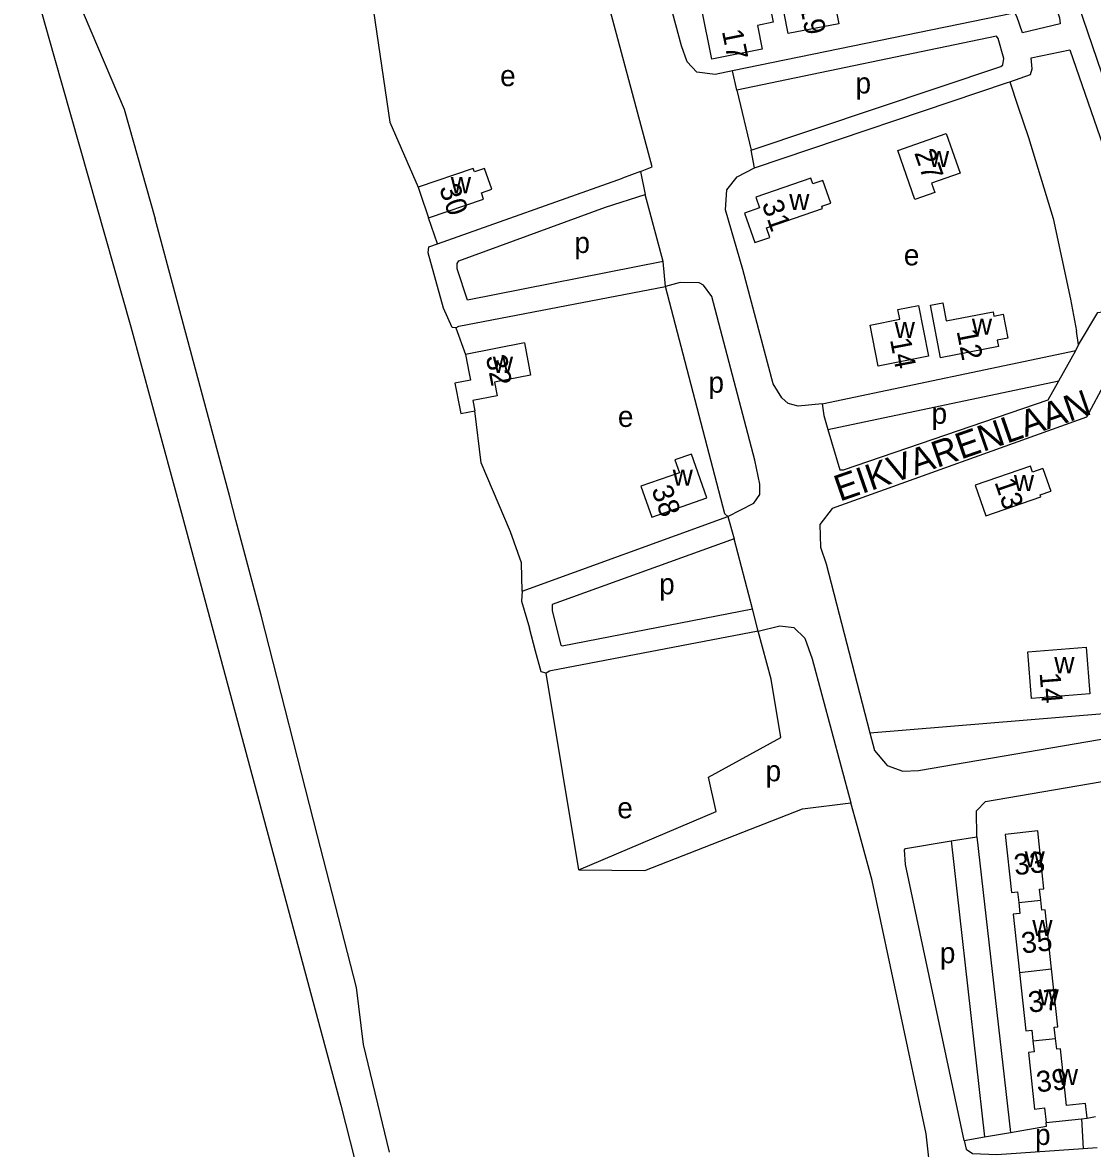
# Model space of a CAD drawing. Extents: x 162667 to 164645, y 379003 to 382150.
# Drawn here: x 162748.4 to 162953, y 380351.9 to 380567.1 of the extents above; entities that cross this region are included whole.
import ezdxf

# ---------------------------------------------------------------- set-up
doc = ezdxf.new("R2010")
doc.units = 0
for name, color, linetype in [('BLT_Basislijn', 7, 'Continuous'), ('BLT_Bebouwing', 7, 'Continuous'), ('BLT_Centroide', 7, 'Continuous'), ('BLT_Huisnummer', 7, 'Continuous'), ('BLT_Onderverdeling_panden', 7, 'Continuous'), ('BLT_Straatnaam', 7, 'Continuous')]:
    doc.layers.add(name, color=color, linetype=linetype)

msp = doc.modelspace()

# ---------------------------------------------------------------- linework, layer by layer
at = {"layer": 'BLT_Basislijn'}
for p, q in [((162885, 380554.15), (162884.15, 380557.88)), ((162885, 380554.15), (162887.73, 380542.69)), ((162937.23, 380555.78), (162938.71, 380551.1)), ((162938.71, 380551.1), (162940.78, 380545.13)), ((162888.4, 380539.33), (162887.73, 380542.69)), ((162866.54, 380538.63), (162863.1, 380537.35)), ((162866.54, 380538.63), (162867.49, 380534.23)), ((162870.88, 380521.4), (162867.49, 380534.23)), ((162777.53, 380515.53), (162773.77, 380529.55)), ((162827.72, 380524.79), (162826.04, 380529.74)), ((162779.18, 380509.37), (162777.53, 380515.53)), ((162948.79, 380514.24), (162949.98, 380508.1)), ((162788.01, 380476.4), (162779.18, 380509.37)), ((162831.23, 380508.73), (162833.08, 380503.66)), ((162950.31, 380505.48), (162949.98, 380508.1)), ((162949.82, 380504.43), (162950.31, 380505.48)), ((162901.33, 380494.19), (162949.82, 380504.43)), ((162946.55, 380498.63), (162949.82, 380504.43)), ((162902.39, 380489.31), (162946.55, 380498.63)), ((162789.2, 380471.99), (162788.01, 380476.4)), ((162843.96, 380458.41), (162883.27, 380472.69)), ((162794.06, 380453.83), (162789.2, 380471.99)), ((162888.01, 380455.04), (162884.51, 380468.41)), ((162889.08, 380450.77), (162888.01, 380455.04)), ((162846.5, 380446.93), (162845.32, 380451.31)), ((162889.08, 380450.77), (162849.44, 380443.15)), ((162891.58, 380441.6), (162889.08, 380450.77)), ((162854.78, 380405.1), (162848.53, 380442.72)), ((162908.01, 380413.59), (162906.8, 380417.91)), ((162925.98, 380410.64), (162930.92, 380411.44)), ((162925.98, 380410.64), (162932.37, 380354.06)), ((162930.92, 380411.44), (162937.3, 380354.9)), ((162937.3, 380354.9), (162944.19, 380356.11)), ((162944.19, 380356.11), (162944.14, 380356.82)), ((162950.88, 380357.55), (162951.2, 380351.88)), ((162952, 380357.67), (162953.61, 380357.95)), ((162928.48, 380353.4), (162932.37, 380354.06)), ((162932.37, 380354.06), (162937.3, 380354.9))]:
    msp.add_line(p, q, dxfattribs=at)
for points in [[(162928.15, 380621.89), (162946.67, 380568), (162946.84, 380566.84), (162939.62, 380565.1), (162938.53, 380568.25), (162938.19, 380568.83), (162937.65, 380568.79), (162884.15, 380557.88)], [(162936.69, 380610.36), (162967.4, 380520.31), (162968.51, 380517.36), (162969.4, 380517.45), (162963.56, 380600.72), (162963.48, 380601.84)], [(162884.15, 380557.88), (162880.85, 380557.13), (162877.35, 380557.61), (162875.5, 380559.58), (162874.39, 380562.61), (162866.41, 380592.44), (162865.65, 380596.55), (162865.67, 380598.15), (162867.28, 380600.7), (162871.18, 380602.46)], [(162748.39, 380581.99), (162754.35, 380560.74), (162769.12, 380508.9), (162778.96, 380472.61)], [(162866.54, 380538.63), (162868.78, 380539.48), (162857.1, 380583.31)], [(162758.91, 380571.59), (162767.84, 380550.54), (162773.77, 380529.55)], [(162815.54, 380569.25), (162818.61, 380548.05), (162824.03, 380535.6)], [(162887.73, 380542.69), (162935.51, 380558.69), (162935.89, 380559.01), (162936.05, 380560.22), (162934.95, 380564.02), (162934.66, 380564.49), (162885, 380554.15)], [(162937.23, 380555.78), (162941.15, 380557.19), (162941.47, 380558.24), (162941.29, 380560.34), (162948.69, 380561.9), (162965.48, 380513.26)], [(162888.4, 380539.33), (162936.77, 380555.61), (162937.23, 380555.78)], [(162940.78, 380545.13), (162945.46, 380529.62), (162948.79, 380514.24)], [(162901.33, 380494.19), (162896.71, 380493.73), (162894.78, 380494.25), (162893.57, 380495.35), (162891.95, 380498.06), (162886.17, 380519.88), (162882.83, 380531.28), (162883.05, 380535.14), (162885.06, 380537.62), (162888.4, 380539.33)], [(162827.72, 380524.79), (162862.22, 380537.03), (162863.1, 380537.35)], [(162870.88, 380521.4), (162833.46, 380514), (162831.53, 380520.01), (162831.52, 380521.02), (162831.84, 380521.56), (162859.87, 380531.77), (162867.49, 380534.23)], [(162831.23, 380508.73), (162830.54, 380508.82), (162828.92, 380512.51), (162825.95, 380523.07), (162826.08, 380524.21), (162827.72, 380524.79)], [(162871.37, 380516.62), (162870.88, 380521.4)], [(162831.23, 380508.73), (162831.81, 380509.06), (162871.37, 380516.62)], [(162883.27, 380472.69), (162888.25, 380475.19), (162889.36, 380476.88), (162889.36, 380478.87), (162888.46, 380483.45), (162880.24, 380514.71), (162878.62, 380516.88), (162877.76, 380517.36), (162874.18, 380517.39), (162871.37, 380516.62)], [(162883.27, 380472.69), (162882.73, 380473.17), (162871.37, 380516.62)], [(162950.31, 380505.48), (162954.06, 380511.67), (162965.48, 380513.26)], [(162955.48, 380498.39), (162951.83, 380491.64), (162903.21, 380474.17), (162900.87, 380471.11), (162901, 380466.81), (162902.05, 380463.65), (162910.44, 380431.3)], [(162902.39, 380489.31), (162904.66, 380481.58), (162905.36, 380481.57), (162944.5, 380495), (162946.55, 380498.63)], [(162901.33, 380494.19), (162901.61, 380491.97), (162902.39, 380489.31)], [(162841.72, 380469.75), (162836.09, 380482.9), (162834.89, 380492.87)], [(162778.96, 380472.61), (162809.27, 380360.13), (162814.71, 380338.87)], [(162883.27, 380472.69), (162884.51, 380468.41)], [(162843.96, 380458.41), (162843.79, 380463.84), (162841.72, 380469.75)], [(162884.51, 380468.41), (162849.68, 380455.85), (162849.68, 380454.63), (162851.34, 380448.1), (162851.6, 380447.94), (162888.01, 380455.04)], [(162843.96, 380458.41), (162843.83, 380456.48), (162845.32, 380451.31)], [(162818.56, 380351.15), (162813.62, 380371.74), (162812.27, 380382.63), (162804.82, 380411.61), (162794.06, 380453.83)], [(162889.08, 380450.77), (162893.19, 380451.79), (162895.89, 380451.43), (162897.97, 380449.4), (162899.4, 380445.49), (162906.8, 380417.91)], [(162910.44, 380431.3), (162955.18, 380435.03), (162955.09, 380438.8), (162955.53, 380438.88), (162996.45, 380442.3), (162996.77, 380442.68), (162996.75, 380446.24), (163038.61, 380449.48)], [(162910.44, 380431.3), (162911.35, 380427.96), (162913.74, 380425.09), (162916.71, 380423.98), (162919.74, 380424.13), (162954.37, 380430.01), (163031.14, 380443.68), (163034.88, 380444.59), (163036.92, 380445.42), (163038.2, 380446.92), (163038.61, 380449.48)], [(162848.53, 380442.72), (162847.59, 380442.99), (162846.5, 380446.93)], [(162849.44, 380443.15), (162849.19, 380443.1), (162848.53, 380442.72)], [(162854.78, 380405.1), (162881.05, 380416.29), (162879.57, 380422.81), (162893.41, 380430.42), (162891.58, 380441.6)], [(162930.92, 380411.44), (162930.8, 380416.43), (162932.55, 380418.18), (162970.08, 380424.65), (162975.1, 380425.17), (162976.67, 380424.93), (162978.44, 380423.02), (162979.49, 380419.64)], [(162854.78, 380405.1), (162867.37, 380404.98), (162897.55, 380416.8), (162906.8, 380417.91)], [(162923.85, 380330.61), (162921.23, 380354.66), (162910.88, 380403.1), (162908.01, 380413.59)], [(162928.48, 380353.4), (162917.27, 380406.15), (162917.06, 380408.95), (162917.25, 380409.22), (162925.98, 380410.64)], [(162928.48, 380353.4), (162928.88, 380351.73), (162930.06, 380350.88), (162934.73, 380350.71), (162951.2, 380351.88)], [(162951.2, 380351.88), (162953.93, 380352.07)]]:
    msp.add_lwpolyline(points, dxfattribs=at)
at = {"layer": 'BLT_Bebouwing'}
for p, q in [((162935.94, 380511.32), (162936.82, 380506.77)), ((162844.37, 380505.85), (162833.08, 380503.66)), ((162943.54, 380481.86), (162945.03, 380477.54)), ((162944.14, 380356.82), (162950.88, 380357.55)), ((162950.88, 380357.55), (162952, 380357.67))]:
    msp.add_line(p, q, dxfattribs=at)
for points in [[(162893.31, 380572.83), (162898.97, 380573.94), (162898.61, 380575.8), (162902.57, 380576.58), (162904.47, 380566.86), (162894.84, 380564.98)], [(162878.24, 380569.9), (162887.77, 380571.77), (162887.21, 380574.61), (162890.35, 380575.24), (162891.96, 380567.16), (162888.92, 380566.55), (162889.83, 380561.98), (162880.23, 380560.07)], [(162915.79, 380542.63), (162925.05, 380545.86), (162927.68, 380538.3), (162922.23, 380536.41), (162922.85, 380534.61), (162919.05, 380533.28)], [(162919.76, 380513.01), (162921.67, 380503.3), (162912.03, 380501.41), (162910.51, 380509.25), (162916.16, 380510.36), (162915.79, 380512.23)], [(162940.64, 380446.8), (162951.8, 380447.67), (162952.5, 380438.75), (162941.34, 380437.87)]]:
    msp.add_lwpolyline(points, close=True, dxfattribs=at)
for points in [[(162838.14, 380535.22), (162836.77, 380539.21), (162834.82, 380538.54), (162834.58, 380539.22), (162824.03, 380535.6)], [(162901.46, 380536.92), (162899.5, 380536.24), (162899.12, 380537.34), (162888.64, 380533.72), (162889.34, 380531.67), (162886.49, 380530.68), (162888.45, 380525.02), (162891.29, 380526), (162890.66, 380527.83), (162901.36, 380531.53), (162901.25, 380531.98), (162902.96, 380532.58)], [(162902.96, 380532.58), (162901.46, 380536.92)], [(162824.03, 380535.6), (162824.42, 380534.47), (162826.04, 380529.74)], [(162826.04, 380529.74), (162836.55, 380533.35), (162836.14, 380534.54), (162838.14, 380535.22)], [(162922.02, 380513.04), (162924.37, 380513.49), (162925.03, 380510.08), (162933.99, 380511.82), (162934.15, 380510.98), (162935.94, 380511.32)], [(162936.82, 380506.77), (162934.77, 380506.37), (162935.01, 380505.16), (162923.96, 380503.01), (162922.02, 380513.04)], [(162844.37, 380505.85), (162845.56, 380499.7), (162838.68, 380498.35), (162839.19, 380495.74), (162834.51, 380494.83), (162834.89, 380492.87)], [(162833.08, 380503.66), (162833.79, 380500), (162834.04, 380498.75), (162831.09, 380498.18), (162832.04, 380493.32), (162832.23, 380492.35), (162834.89, 380492.87)], [(162868.73, 380472.54), (162879.28, 380476.26), (162876.34, 380484.59), (162873.16, 380483.47), (162874.02, 380481.04), (162866.65, 380478.44), (162868.73, 380472.54)], [(162943.54, 380481.86), (162941.53, 380481.17), (162941.15, 380482.29), (162930.57, 380478.65), (162932.59, 380472.77)], [(162932.59, 380472.77), (162943.14, 380476.4), (162942.99, 380476.84), (162945.03, 380477.54)], [(162943.13, 380399.31), (162942.9, 380401.42), (162943.73, 380401.52), (162943.07, 380407.6), (162942.53, 380412.57), (162936.33, 380411.89), (162937.54, 380400.8), (162938.68, 380400.92), (162938.91, 380398.85)], [(162945.17, 380386.17), (162943.94, 380397.47), (162943.34, 380397.4), (162943.13, 380399.31)], [(162938.91, 380398.85), (162939.13, 380396.78), (162937.82, 380396.64), (162939.04, 380385.51)], [(162945.94, 380372.89), (162945.7, 380375.06), (162946.37, 380375.13), (162945.17, 380386.17)], [(162939.04, 380385.51), (162940.25, 380374.37), (162941.4, 380374.5), (162941.62, 380372.42)], [(162941.62, 380372.42), (162941.85, 380370.34), (162940.74, 380370.22), (162941.92, 380359.39), (162943.83, 380359.6), (162944.14, 380356.82)], [(162952, 380357.67), (162951.7, 380360.47), (162948.05, 380360.08), (162946.87, 380370.93), (162946.16, 380370.85), (162945.94, 380372.89)]]:
    msp.add_lwpolyline(points, dxfattribs=at)
at = {"layer": 'BLT_Onderverdeling_panden'}
for p, q in [((162938.91, 380398.85), (162943.13, 380399.31)), ((162939.04, 380385.51), (162945.17, 380386.17)), ((162941.62, 380372.42), (162945.94, 380372.89))]:
    msp.add_line(p, q, dxfattribs=at)

# ---------------------------------------------------------------- texts
at = {"layer": 'BLT_Centroide'}
for s, p in [('e', (162839.73, 380554.94)), ('p', (162907.69, 380553.54)), ('w', (162921.73, 380539.47)), ('w', (162830.29, 380534.47)), ('w', (162895.01, 380531.25)), ('p', (162853.94, 380523.04)), ('e', (162916.93, 380520.67)), ('w', (162915.18, 380506.76)), ('w', (162929.94, 380507.41)), ('w', (162838.33, 380500.12)), ('p', (162879.57, 380496.33)), ('e', (162862.25, 380489.79)), ('p', (162922.24, 380490.39)), ('w', (162872.73, 380478.56)), ('w', (162937.97, 380477.53)), ('p', (162870.14, 380457.79)), ('w', (162945.7, 380442.72)), ('p', (162890.49, 380422.05)), ('e', (162862.13, 380414.98)), ('w', (162940.03, 380405.62)), ('w', (162941.5, 380392.45)), ('p', (162923.82, 380387.27)), ('w', (162942.7, 380379.22)), ('w', (162946.38, 380363.97)), ('p', (162942.02, 380352.53))]:
    msp.add_text(s, height=4, dxfattribs=at).set_placement(p)
at = {"layer": 'BLT_Huisnummer'}
for s, rotation, p in [('19', 281.432, (162897.02, 380570.32)), ('17', 281.432, (162882.12, 380565.45)), ('27', 289.2073, (162918.88, 380542.2)), ('30', 288.9169, (162828.02, 380535.47)), ('31', 289.0643, (162889.73, 380532.45)), ('12', 280.988, (162927.01, 380508.12)), ('14', 280.7764, (162914.27, 380506.48)), ('32', 280.9779, (162836.98, 380503.22)), ('38', 289.4133, (162868.62, 380477.85)), ('13', 288.99, (162934.23, 380479.25)), ('14', 274.4734, (162942.89, 380442.74)), ('33', 6.2195, (162938.19, 380404.08)), ('35', 6.2161, (162939.59, 380389.12)), ('37', 6.2163, (162940.9, 380377.81)), ('39', 6.2126, (162942.45, 380362.58))]:
    msp.add_text(s, height=4, rotation=rotation, dxfattribs=at).set_placement(p)
at = {"layer": 'BLT_Straatnaam'}
msp.add_text('EIKVARENLAAN', height=4.9999, rotation=19.1406, dxfattribs=at).set_placement((162904.68, 380475.49))

doc.saveas('drawing.dxf')
